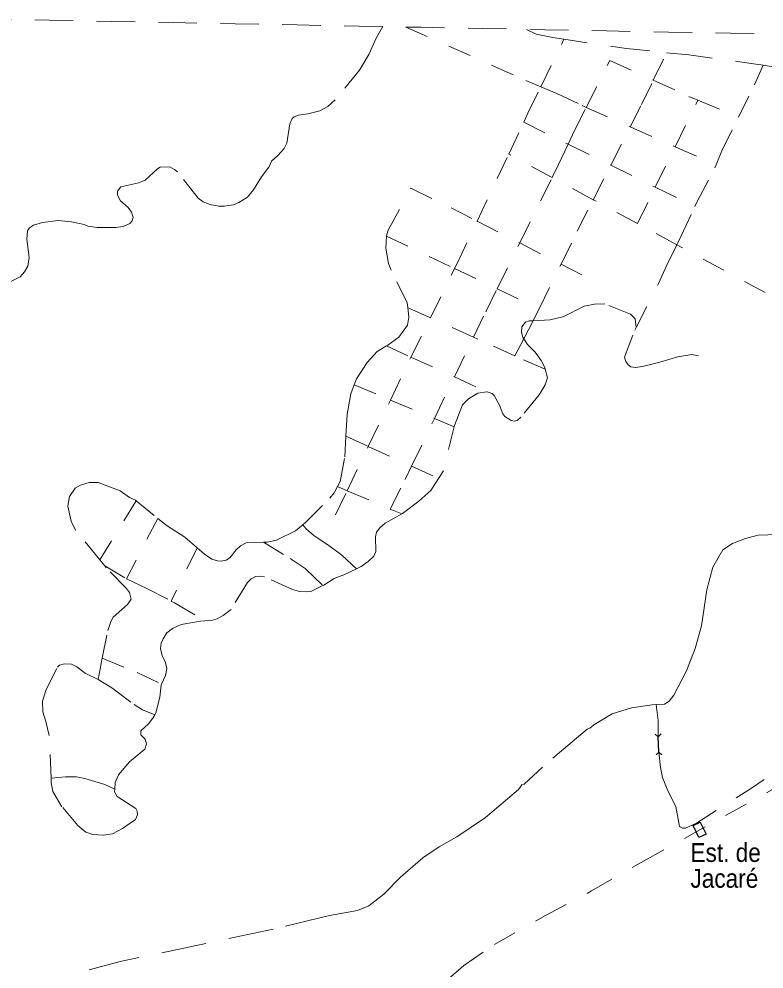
# Model space of a CAD drawing. Extents: x 783.4 to 809.8, y 7536.4 to 7564.6.
# Drawn here: x 801.476 to 804.649, y 7560.221 to 7564.265 of the extents above; entities that cross this region are included whole.
import ezdxf

# ---------------------------------------------------------------- set-up
doc = ezdxf.new("R2010")
doc.units = 0
doc.header["$LTSCALE"] = 0.032
for name, pattern in [('DOTTED', [1.5, 0.3, -1.2]), ('LONG_DASHED', [7.5, 6, -1.5]), ('MEDIUM_DASHED', [4.5, 3, -1.5]), ('SHORT_DASHED', [2.7, 1.5, -1.2])]:
    doc.linetypes.add(name, pattern=pattern)
for name, color, linetype, lineweight in [('18', 7, 'DOTTED', 13), ('28', 7, 'Continuous', 25), ('31', 7, 'Continuous', 25), ('35', 7, 'SHORT_DASHED', 13), ('5', 7, 'LONG_DASHED', 13), ('6', 7, 'MEDIUM_DASHED', 13), ('7', 7, 'DOTTED', 13)]:
    doc.layers.add(name, color=color, linetype=linetype, lineweight=lineweight)
doc.layers.add('61', color=7, linetype='Continuous')

msp = doc.modelspace()

# ---------------------------------------------------------------- linework, layer by layer
at = {"layer": '18'}
msp.add_lwpolyline([(803.3041, 7560.178), (803.3697, 7560.2358), (803.501, 7560.326), (803.7185, 7560.4491), (803.9144, 7560.5539), (804.1349, 7560.6807), (804.7152, 7561.0021)], dxfattribs=at)
at = {"layer": '28'}
msp.add_lwpolyline([(804.3716, 7560.781), (804.3466, 7560.8323), (804.3771, 7560.8471), (804.4021, 7560.7959)], close=True, dxfattribs=at)
at = {"layer": '31'}
for p, q in [((804.1982, 7561.2098), (804.1854, 7561.2217)), ((804.2101, 7561.2227), (804.1982, 7561.2098)), ((804.2009, 7561.1451), (804.1982, 7561.2098)), ((804.2009, 7561.1451), (804.1889, 7561.1324)), ((804.2137, 7561.1334), (804.2009, 7561.1451))]:
    msp.add_line(p, q, dxfattribs=at)
at = {"layer": '35'}
msp.add_lwpolyline([(801.3431, 7564.265), (801.6067, 7564.26), (801.8703, 7564.2549), (802.1338, 7564.2498), (802.3974, 7564.2448), (802.661, 7564.2397), (802.9246, 7564.2347), (803.1882, 7564.2296), (803.4518, 7564.2246), (803.7154, 7564.2195), (803.9789, 7564.2144), (804.2425, 7564.2094), (804.5061, 7564.2043), (804.7697, 7564.1992)], dxfattribs=at)
at = {"layer": '5'}
for points in [[(804.7054, 7562.071), (804.6238, 7562.0678), (804.5694, 7562.0542), (804.515, 7562.0326), (804.4736, 7562.0054), (804.431, 7561.9318), (804.4054, 7561.8358), (804.3822, 7561.6822), (804.3558, 7561.5861), (804.3182, 7561.4901), (804.2646, 7561.3869), (804.2446, 7561.3621), (804.2254, 7561.3493), (804.1894, 7561.3471)], [(804.1894, 7561.3471), (804.1726, 7561.3461), (804.0846, 7561.3325), (804.0022, 7561.3077), (803.9246, 7561.2613), (803.907, 7561.2469), (803.8958, 7561.2429), (803.7054, 7561.0805), (803.6278, 7561.0077), (803.6174, 7561.0053), (803.6038, 7560.9861), (803.463, 7560.8669), (803.341, 7560.7841), (803.2653, 7560.7413), (803.1957, 7560.6949), (803.1013, 7560.6125), (803.0301, 7560.5405), (802.9661, 7560.4909), (802.9181, 7560.4709), (802.7981, 7560.4485), (802.5581, 7560.3909), (801.9064, 7560.2531), (801.7757, 7560.2181)]]:
    msp.add_lwpolyline(points, dxfattribs=at)
at = {"layer": '6'}
for points in [[(803.6379, 7564.221), (803.6782, 7564.2005), (803.75, 7564.1863), (803.7969, 7564.1792)], [(803.7969, 7564.1792), (804.0626, 7564.139), (804.2336, 7564.1216)], [(804.2336, 7564.1216), (804.3285, 7564.1119), (804.5937, 7564.0759), (804.6453, 7564.0679)], [(804.6453, 7564.0679), (804.8376, 7564.0379), (804.9464, 7564.0275), (804.9915, 7564.0261), (805.0084, 7564.0228)], [(804.1894, 7561.3471), (804.1976, 7561.2797), (804.1982, 7561.2098), (804.2009, 7561.1451), (804.2079, 7561.0795), (804.2161, 7561.0365), (804.2397, 7560.9796), (804.2738, 7560.9137), (804.289, 7560.8287), (804.3009, 7560.8204), (804.3149, 7560.8211), (804.3608, 7560.8426), (804.5916, 7560.9883), (804.649, 7561.0282)]]:
    msp.add_lwpolyline(points, dxfattribs=at)
at = {"layer": '7'}
for p, q in [((803.6984, 7563.9768), (803.7969, 7564.1792)), ((804.1772, 7564.0043), (804.2336, 7564.1216)), ((804.2703, 7563.7215), (804.3673, 7563.9194)), ((804.3673, 7563.9194), (804.5398, 7563.8466)), ((803.8912, 7563.8889), (804.0792, 7563.8059)), ((803.5614, 7563.6902), (803.6252, 7563.8253)), ((803.6252, 7563.8253), (803.8142, 7563.7322)), ((803.9961, 7563.6425), (804.0792, 7563.8059)), ((804.0792, 7563.8059), (804.2703, 7563.7215)), ((803.8142, 7563.7322), (803.9961, 7563.6425)), ((804.1858, 7563.5491), (804.2703, 7563.7215)), ((804.2703, 7563.7215), (804.4451, 7563.6443)), ((803.4267, 7563.4047), (803.5614, 7563.6902)), ((803.7465, 7563.5903), (803.5614, 7563.6902)), ((803.9215, 7563.4959), (803.9961, 7563.6425)), ((803.9961, 7563.6425), (804.1858, 7563.5491)), ((803.6084, 7563.3116), (803.7465, 7563.5903)), ((803.9215, 7563.4959), (803.7465, 7563.5903)), ((804.1099, 7563.3942), (804.1858, 7563.5491)), ((804.1858, 7563.5491), (804.3535, 7563.4664)), ((804.1099, 7563.3942), (803.9215, 7563.4959)), ((803.4267, 7563.4047), (803.6084, 7563.3116)), ((804.2771, 7563.304), (804.1099, 7563.3942)), ((803.0418, 7563.3405), (803.331, 7563.203)), ((803.5119, 7563.117), (803.6084, 7563.3116)), ((803.6084, 7563.3116), (803.7844, 7563.2214)), ((804.6536, 7563.1008), (804.2771, 7563.304)), ((803.7844, 7563.2214), (803.8968, 7563.1638)), ((803.2279, 7562.9934), (803.331, 7563.203)), ((803.331, 7563.203), (803.5119, 7563.117)), ((803.5119, 7563.117), (803.6913, 7563.0317)), ((803.2279, 7562.9934), (803.1314, 7563.0371)), ((803.1453, 7562.8257), (803.2279, 7562.9934)), ((803.4113, 7562.9105), (803.2279, 7562.9934)), ((803.6257, 7562.9042), (803.6656, 7562.9809)), ((803.3301, 7562.7415), (803.4113, 7562.9105)), ((803.5879, 7562.8315), (803.6257, 7562.9042)), ((803.0407, 7562.8733), (803.1453, 7562.8257)), ((803.1453, 7562.8257), (803.3301, 7562.7415)), ((803.7163, 7562.7742), (803.5879, 7562.8315)), ((803.2453, 7562.5647), (803.3301, 7562.7415)), ((803.3301, 7562.7415), (803.4683, 7562.6785)), ((802.9032, 7562.7078), (803.0579, 7562.6431)), ((802.9636, 7562.4456), (803.0579, 7562.6431)), ((803.0579, 7562.6431), (803.2453, 7562.5647)), ((803.1477, 7562.3615), (803.2453, 7562.5647)), ((803.2453, 7562.5647), (803.3291, 7562.5296)), ((802.8682, 7562.4892), (802.9636, 7562.4456)), ((802.8735, 7562.2572), (802.9636, 7562.4456)), ((802.9636, 7562.4456), (803.1477, 7562.3615)), ((803.1477, 7562.3615), (803.2626, 7562.309)), ((802.8245, 7562.1546), (802.8735, 7562.2572)), ((802.8325, 7562.2747), (802.8735, 7562.2572)), ((801.9748, 7562.2148), (801.8209, 7561.9626)), ((802.0673, 7562.1395), (801.9336, 7561.8824)), ((802.2345, 7562.0143), (802.1241, 7561.7877)), ((801.8413, 7561.9377), (801.9336, 7561.8824)), ((801.8129, 7561.4539), (801.831, 7561.545))]:
    msp.add_line(p, q, dxfattribs=at)
for points in [[(803.0256, 7564.2327), (802.9988, 7564.1865), (802.9658, 7564.114), (802.9266, 7564.0473), (802.8225, 7563.9207), (802.7916, 7563.8926), (802.7575, 7563.8743), (802.706, 7563.8617), (802.6658, 7563.8559), (802.6482, 7563.8491), (802.639, 7563.8414), (802.6297, 7563.8182), (802.6163, 7563.737), (802.606, 7563.7138), (802.5787, 7563.6834), (802.5519, 7563.6602), (802.5397, 7563.6349), (802.5093, 7563.5933), (802.4753, 7563.5377), (802.4487, 7563.5065), (802.4117, 7563.4836), (802.3895, 7563.4739), (802.3503, 7563.4677), (802.3274, 7563.4684), (802.2889, 7563.476), (802.2608, 7563.4871), (802.2386, 7563.5031), (802.151, 7563.6138), (802.1384, 7563.6249), (802.1184, 7563.6353), (802.0774, 7563.635), (802.0655, 7563.6273), (802.0137, 7563.5795), (801.9871, 7563.5677), (801.9094, 7563.5503), (801.8961, 7563.5323), (801.8954, 7563.5156), (801.9087, 7563.4907), (801.9405, 7563.4629), (801.956, 7563.4435), (801.9627, 7563.4206), (801.9583, 7563.406), (801.9479, 7563.3942), (801.9205, 7563.3824), (801.8887, 7563.3782), (801.8088, 7563.3776), (801.7689, 7563.3838), (801.7541, 7563.39), (801.7005, 7563.4015), (801.6427, 7563.4078), (801.5769, 7563.3995), (801.5377, 7563.387), (801.5207, 7563.3766), (801.5125, 7563.3634), (801.5103, 7563.328), (801.5199, 7563.2503), (801.514, 7563.2135), (801.4999, 7563.1886), (801.4807, 7563.1677), (801.4363, 7563.1455)], [(803.1231, 7564.2309), (803.6345, 7564.0035), (803.6984, 7563.9768)], [(803.8912, 7563.8889), (803.9919, 7564.0882), (804.1772, 7564.0043)], [(804.5398, 7563.8466), (804.608, 7563.9847), (804.6453, 7564.0679)], [(804.0792, 7563.8059), (804.1275, 7563.9009), (804.1772, 7564.0043)], [(804.1772, 7564.0043), (804.3286, 7563.9357), (804.3673, 7563.9194)], [(803.6252, 7563.8253), (803.6434, 7563.8638), (803.6984, 7563.9768)], [(803.6984, 7563.9768), (803.7668, 7563.9483), (803.8736, 7563.8966), (803.8912, 7563.8889)], [(803.8142, 7563.7322), (803.8413, 7563.7902), (803.8912, 7563.8889)], [(804.4451, 7563.6443), (804.469, 7563.7033), (804.5398, 7563.8466)], [(803.7465, 7563.5903), (803.7737, 7563.6452), (803.8142, 7563.7322)], [(804.3535, 7563.4664), (804.3649, 7563.491), (804.4398, 7563.6311), (804.4451, 7563.6443)], [(803.0418, 7563.3405), (803.0423, 7563.3476), (803.0486, 7563.3668), (803.145, 7563.5454), (803.3159, 7563.4615), (803.4267, 7563.4047)], [(803.7844, 7563.2214), (803.8532, 7563.3615), (803.9215, 7563.4959)], [(804.2771, 7563.304), (804.2961, 7563.3421), (804.3535, 7563.4664)], [(803.331, 7563.203), (803.3402, 7563.2216), (803.4267, 7563.4047)], [(803.1314, 7563.0371), (803.1291, 7563.0566), (803.0603, 7563.1961), (803.05, 7563.2238), (803.0386, 7563.29), (803.0418, 7563.3405)], [(804.1046, 7562.9521), (804.1993, 7563.1388), (804.2341, 7563.2178), (804.2771, 7563.304)], [(803.6656, 7562.9809), (803.679, 7563.0066), (803.6913, 7563.0317), (803.7844, 7563.2214)], [(803.4113, 7562.9105), (803.4634, 7563.0191), (803.5119, 7563.117)], [(804.1046, 7562.9521), (804.0999, 7562.9892), (804.0806, 7563.0081), (803.9702, 7563.0526), (803.9262, 7563.051), (803.883, 7563.0422), (803.7926, 7562.9974), (803.7374, 7562.9846), (803.6656, 7562.9809)], [(803.0407, 7562.8733), (803.0473, 7562.8773), (803.0939, 7562.9106), (803.1302, 7562.9619), (803.1361, 7562.9966), (803.1314, 7563.0371)], [(803.6656, 7562.9809), (803.6491, 7562.98), (803.6335, 7562.9744), (803.618, 7562.9543), (803.6165, 7562.93), (803.621, 7562.9113), (803.6257, 7562.9042)], [(804.3694, 7562.832), (804.341, 7562.8373), (804.2819, 7562.8274), (804.2049, 7562.8039), (804.1312, 7562.7857), (804.102, 7562.7819), (804.0818, 7562.7841), (804.0696, 7562.7933), (804.0607, 7562.8069), (804.055, 7562.8252), (804.0988, 7562.9406), (804.1046, 7562.9521)], [(803.5879, 7562.8315), (803.4304, 7562.9018), (803.4113, 7562.9105)], [(803.6257, 7562.9042), (803.6417, 7562.8801), (803.6735, 7562.8475), (803.7001, 7562.8121), (803.7134, 7562.785), (803.7163, 7562.7742)], [(802.9032, 7562.7078), (802.913, 7562.7333), (802.9593, 7562.803), (803.0015, 7562.8495), (803.0407, 7562.8733)], [(803.0579, 7562.6431), (803.141, 7562.8169), (803.1453, 7562.8257)], [(803.7163, 7562.7742), (803.726, 7562.7372), (803.7168, 7562.7077), (803.6917, 7562.6647), (803.6132, 7562.5703), (803.5977, 7562.5565), (803.5859, 7562.5537), (803.5725, 7562.5558), (803.5452, 7562.5731), (803.537, 7562.5842), (803.5222, 7562.621), (803.4997, 7562.6629), (803.4908, 7562.6712), (803.4701, 7562.6788), (803.4683, 7562.6785)], [(802.8682, 7562.4892), (802.8738, 7562.5835), (802.8886, 7562.6695), (802.9032, 7562.7078)], [(803.4683, 7562.6785), (803.4294, 7562.6726), (803.3902, 7562.649), (803.365, 7562.6233), (803.3303, 7562.5345), (803.3291, 7562.5296)], [(803.3291, 7562.5296), (803.2841, 7562.342), (803.2626, 7562.309)], [(802.8325, 7562.2747), (802.8438, 7562.2959), (802.863, 7562.4014), (802.8682, 7562.4892)], [(803.0569, 7562.1792), (803.1203, 7562.3044), (803.1477, 7562.3615)], [(801.8209, 7561.9626), (801.717, 7562.0891), (801.6978, 7562.1272), (801.6844, 7562.1913), (801.6918, 7562.2323), (801.7154, 7562.2683), (801.7384, 7562.2808), (801.7754, 7562.2919), (801.8138, 7562.2919), (801.907, 7562.2572), (801.947, 7562.2281), (801.9721, 7562.217), (801.9748, 7562.2148), (802.0673, 7562.1395)], [(803.2626, 7562.309), (803.2293, 7562.2581), (803.179, 7562.2123), (803.1087, 7562.1596), (803.1062, 7562.1582)], [(802.6844, 7562.1119), (802.6976, 7562.1228), (802.8004, 7562.2262), (802.8182, 7562.2477), (802.8325, 7562.2747)], [(802.8735, 7562.2572), (803.0569, 7562.1792), (803.1062, 7562.1582)], [(802.0673, 7562.1395), (802.1072, 7562.1071), (802.1828, 7562.059), (802.2345, 7562.0143)], [(803.1062, 7562.1582), (803.0359, 7562.1197), (803.013, 7562.0989), (802.9989, 7562.0802), (802.9937, 7562.0614), (802.996, 7561.999), (802.9871, 7561.9782), (802.9627, 7561.9553), (802.9331, 7561.9352), (802.9128, 7561.9252)], [(802.517, 7562.0376), (802.5326, 7562.0381), (802.5733, 7562.0472), (802.6532, 7562.086), (802.6844, 7562.1119)], [(802.9128, 7561.9252), (802.8504, 7561.9828), (802.7953, 7562.0243), (802.7331, 7562.0652), (802.6985, 7562.0952), (802.6844, 7562.1119)], [(802.2345, 7562.0143), (802.2666, 7561.9865), (802.297, 7561.9657), (802.3221, 7561.9581), (802.3377, 7561.9574), (802.3584, 7561.9615), (802.3739, 7561.9712), (802.4005, 7562.0059), (802.4198, 7562.0233), (802.4434, 7562.0351), (802.517, 7562.0376)], [(802.517, 7562.0376), (802.6306, 7561.969), (802.6947, 7561.9257), (802.7698, 7561.8531)], [(801.831, 7561.545), (801.8544, 7561.6627), (801.8669, 7561.7002), (801.8773, 7561.7189), (801.9384, 7561.7727), (801.9532, 7561.7963), (801.9473, 7561.8233), (801.9339, 7561.8407), (801.8481, 7561.9295), (801.8413, 7561.9377), (801.8209, 7561.9626)], [(802.9128, 7561.9252), (802.8599, 7561.8991), (802.8189, 7561.8842), (802.7738, 7561.855), (802.7698, 7561.8531)], [(801.9336, 7561.8824), (801.9369, 7561.8804), (802.0208, 7561.8411), (802.1241, 7561.7877)], [(802.7698, 7561.8531), (802.7183, 7561.8287), (802.6998, 7561.8266), (802.6709, 7561.8287), (802.6406, 7561.837), (802.522, 7561.8908), (802.5035, 7561.8942), (802.4835, 7561.8915), (802.4643, 7561.8825), (802.4487, 7561.8672), (802.3799, 7561.752), (802.3459, 7561.7257), (802.3207, 7561.7125), (802.3008, 7561.7069), (802.2673, 7561.7036)], [(802.1241, 7561.7877), (802.1391, 7561.7799), (802.2673, 7561.7036)], [(802.2673, 7561.7036), (802.2491, 7561.7018), (802.1665, 7561.6871), (802.1295, 7561.6712), (802.1058, 7561.6517), (802.0895, 7561.6274), (802.0821, 7561.608), (802.0792, 7561.5851), (802.0858, 7561.556), (802.1006, 7561.5255), (802.1051, 7561.5005), (802.0999, 7561.4707), (802.0827, 7561.4343)], [(801.613, 7561.0339), (801.6046, 7561.2148), (801.5906, 7561.2744), (801.5772, 7561.3154), (801.5765, 7561.3618), (801.5913, 7561.4111), (801.6405, 7561.5065), (801.6494, 7561.5141), (801.6701, 7561.5204), (801.7005, 7561.519), (801.7227, 7561.5072), (801.7574, 7561.4808), (801.8129, 7561.4539)], [(801.831, 7561.545), (801.9791, 7561.4832), (802.0827, 7561.4343)], [(801.8129, 7561.4539), (801.872, 7561.4181), (801.9663, 7561.3469), (802.0015, 7561.3244), (802.0541, 7561.3031)], [(802.0827, 7561.4343), (802.0814, 7561.4316), (802.0759, 7561.3787), (802.0589, 7561.3121), (802.0541, 7561.3031)], [(802.0541, 7561.3031), (802.0463, 7561.2885), (802.0271, 7561.2644), (801.9945, 7561.2359), (801.9953, 7561.2179), (802.013, 7561.1992), (802.0197, 7561.1797), (802.0126, 7561.1578), (801.9461, 7561.103), (801.9002, 7561.0482), (801.8854, 7561.0156), (801.8838, 7560.9868)], [(801.613, 7561.0339), (801.6749, 7561.0396), (801.7211, 7561.039), (801.7565, 7561.0321), (801.8415, 7561.0064), (801.8838, 7560.9868)], [(801.8838, 7560.9868), (801.8832, 7560.9761), (801.895, 7560.956), (801.9738, 7560.9043), (801.9797, 7560.8932), (801.9812, 7560.8779), (801.972, 7560.8571), (801.9175, 7560.8193), (801.8746, 7560.7971), (801.8354, 7560.7908), (801.791, 7560.7936), (801.7607, 7560.804), (801.7266, 7560.8318), (801.6593, 7560.9123), (801.6198, 7560.9765), (801.6139, 7561.0146), (801.613, 7561.0339)]]:
    msp.add_lwpolyline(points, dxfattribs=at)

# ---------------------------------------------------------------- texts
at = {"layer": '61', "width": 0.9}
for s, p in [('Est. de', (804.3354, 7560.6772)), ('Jacaré', (804.3354, 7560.5672))]:
    msp.add_text(s, height=0.08, dxfattribs=at).set_placement(p)

doc.saveas('drawing.dxf')
